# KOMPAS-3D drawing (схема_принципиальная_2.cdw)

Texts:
  Текст на чертеже
  Размерные надписи
  Шероховатость
  Линия-выноска #1
  Линия-выноска #2
  Линия-выноска #3
  Отклонения формы и база
  Заголовок таблицы
  Ячейка таблицы
  Стрелка вида
  Обозначение изменения
  Фигурная скобка
  Номер узла
  Марка координационной оси
  VRCB
  Выносная надпись
  Обозначение узла
  Марка/позиционное обозначение с линией-выноской
  Марка/позиционное обозначение на линии
  Марка/позиционное обозначение без линии-выноски
Dimensions and other numbers on the sheet: 7; 1:1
